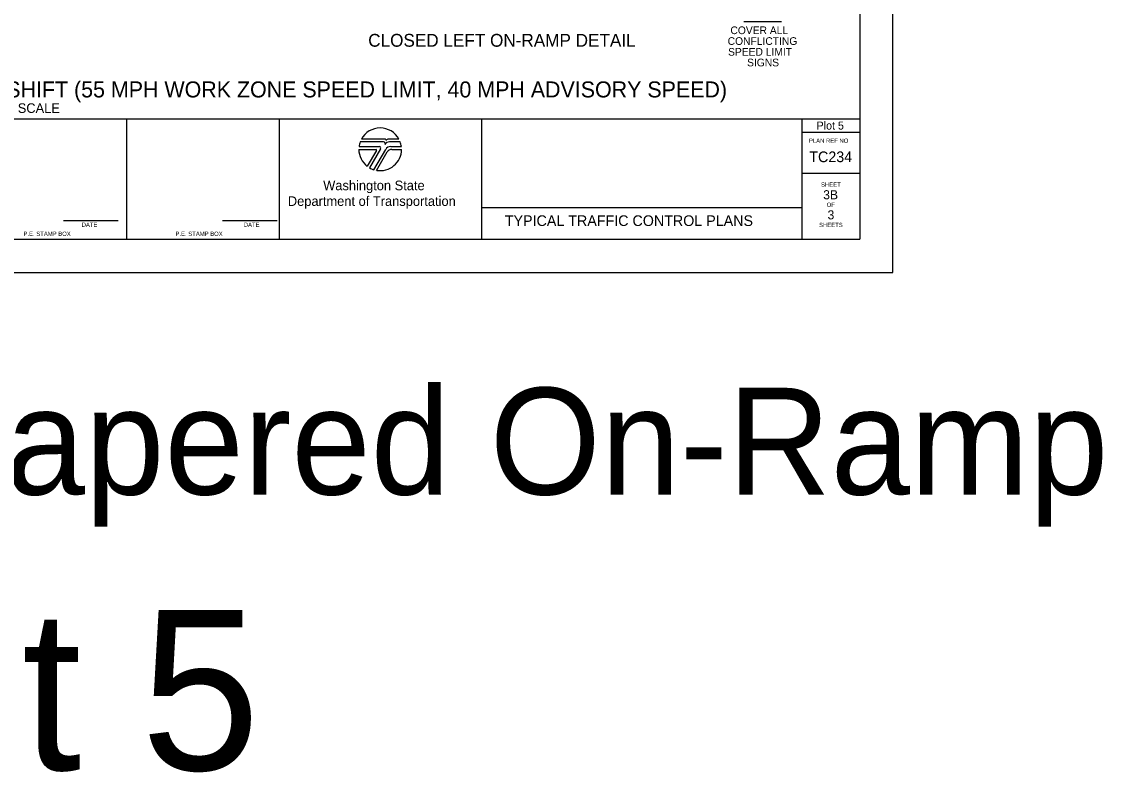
# Model space of a CAD drawing. Extents: x 99999 to 100116, y 99995 to 100013.
# Drawn here: x 100087.9 to 100098.02, y 99995.01 to 100002.04 of the extents above; entities that cross this region are included whole.
import ezdxf

# ---------------------------------------------------------------- set-up
doc = ezdxf.new("R2010")
doc.units = 0
for name, color, linetype in [('Default', 7, 'Continuous'), ('SH_DE_DetailHeading1Text', 7, 'Continuous'), ('SH_DE_DetailHeading2Text', 7, 'Continuous'), ('SH_GI_PlotLimits', 7, 'Continuous'), ('SH_GI_SheetBorder', 7, 'Continuous'), ('SH_GI_SheetLocationText', 7, 'Continuous'), ('SH_GI_SheetTextInCells', 7, 'Continuous'), ('SH_GI_TitleBlockText', 7, 'Continuous'), ('SH_GI_WSDOTLogo', 7, 'Continuous'), ('TR_SN_ConstructionSigns', 7, 'Continuous')]:
    doc.layers.add(name, color=color, linetype=linetype)

msp = doc.modelspace()

# ---------------------------------------------------------------- linework, layer by layer
at = {"layer": 'Default'}
msp.add_line((100094.663, 100002.036), (100095.018, 100002.036), dxfattribs=at)
at = {"layer": 'SH_GI_PlotLimits'}
msp.add_lwpolyline([(100079.062, 99999.687), (100096.062, 99999.687), (100096.062, 100010.687), (100079.062, 100010.687)], close=True, dxfattribs=at)
at = {"layer": 'SH_GI_SheetBorder'}
for p, q in [((100095.75, 100010.375), (100095.75, 100000)), ((100080, 100001.126), (100095.75, 100001.126)), ((100088.883, 100000), (100088.883, 100001.126)), ((100090.309, 100001.126), (100090.309, 100000)), ((100092.205, 100001.126), (100092.205, 100000)), ((100095.208, 100001.126), (100095.208, 100000)), ((100095.208, 100001.001), (100095.75, 100001.001)), ((100095.208, 100000.618), (100095.75, 100000.618)), ((100092.205, 100000.295), (100095.208, 100000.295)), ((100088.29, 100000.173), (100088.802, 100000.173)), ((100089.78, 100000.173), (100090.291, 100000.173)), ((100080, 100000), (100095.75, 100000))]:
    msp.add_line(p, q, dxfattribs=at)
at = {"layer": 'SH_GI_WSDOTLogo'}
for p, q in [((100091.059, 100000.866), (100091.25, 100000.866)), ((100091.289, 100000.909), (100091.07, 100000.909)), ((100091.303, 100000.935), (100091.081, 100000.935)), ((100091.433, 100000.935), (100091.335, 100000.935)), ((100091.445, 100000.909), (100091.343, 100000.909)), ((100091.343, 100000.909), (100091.343, 100000.909)), ((100091.356, 100000.866), (100091.456, 100000.866)), ((100091.057, 100000.84), (100091.215, 100000.84)), ((100091.222, 100000.828), (100091.136, 100000.681)), ((100091.261, 100000.846), (100091.157, 100000.667)), ((100091.199, 100000.649), (100091.309, 100000.839)), ((100091.224, 100000.643), (100091.324, 100000.816)), ((100091.365, 100000.839), (100091.457, 100000.839))]:
    msp.add_line(p, q, dxfattribs=at)
for centre, radius, start, end in [((100091.257, 100000.84), 0.2, 28.4787, 151.532), ((100091.257, 100000.84), 0.2, 159.696, 172.5057), ((100091.25, 100000.853), 0.0131, 329.7683, 90), ((100091.289, 100000.895), 0.0148, 327.8418, 89.9985), ((100091.343, 100000.861), 0.0484, 89.9953, 147.8238), ((100091.303, 100000.926), 0.00903, 329.8742, 90.0033), ((100091.356, 100000.812), 0.0542, 90, 149.9974), ((100091.335, 100000.907), 0.0287, 90.0072, 148.1676), ((100091.257, 100000.84), 0.2, 7.4943, 20.2941), ((100091.257, 100000.84), 0.2, 179.9986, 232.8433), ((100091.215, 100000.832), 0.0082, 329.7436, 90), ((100091.257, 100000.84), 0.2, 260.5455, 359.8086), ((100091.365, 100000.792), 0.0476, 90, 150.0543), ((100091.257, 100000.84), 0.2, 239.7929, 253.0448)]:
    msp.add_arc(centre, radius, start, end, dxfattribs=at)

# ---------------------------------------------------------------- texts
at = {"layer": 'SH_DE_DetailHeading1Text'}
for s, height, p in [("FREEWAY (2 LANES): SINGLE LEFT LANE CLOSURE, 9' MAX RIGHT SHOULDER SHIFT (55 MPH WORK ZONE SPEED LIMIT, 40 MPH ADVISORY SPEED)", 0.15, (100080.091, 100001.326)), ('NOT TO SCALE', 0.09, (100087.373, 100001.181))]:
    msp.add_text(s, height=height, rotation=360, dxfattribs=at).set_placement(p)
at = {"layer": 'SH_DE_DetailHeading2Text'}
msp.add_text('CLOSED LEFT ON-RAMP DETAIL', height=0.12, rotation=360, dxfattribs=at).set_placement((100091.145, 100001.801))
at = {"layer": 'SH_GI_SheetBorder'}
msp.add_text('PLAN REF NO', height=0.04003, dxfattribs=at).set_placement((100095.275, 100000.901))
at = {"layer": 'SH_GI_SheetLocationText'}
for s, height, p in [('Plot 5', 0.075, (100095.346, 100001.025)), ('Left Ramps: Tapered On-Ramp', 1, (100079.351, 99997.607)), ('Plot 5', 1.5, (100085.001, 99995.027))]:
    msp.add_text(s, height=height, dxfattribs=at).set_placement(p)
at = {"layer": 'SH_GI_SheetTextInCells'}
for s, height, p in [('Washington State', 0.09007, (100090.723, 100000.457)), ('SHEET', 0.04, (100095.388, 100000.49)), ('Department of Transportation', 0.09007, (100090.392, 100000.31)), ('OF', 0.04, (100095.441, 100000.301)), ('DATE', 0.04, (100088.46, 100000.114)), ('DATE', 0.04, (100089.979, 100000.114)), ('SHEETS', 0.04, (100095.37, 100000.112)), ('P.E. STAMP BOX', 0.04003, (100087.915, 100000.029)), ('P.E. STAMP BOX', 0.04003, (100089.339, 100000.029))]:
    msp.add_text(s, height=height, dxfattribs=at).set_placement(p)
at = {"layer": 'SH_GI_TitleBlockText'}
for s, height, p in [('TC234', 0.1, (100095.278, 100000.72)), ('3B', 0.085, (100095.408, 100000.372)), ('3', 0.085, (100095.449, 100000.184)), ('TYPICAL TRAFFIC CONTROL PLANS', 0.1, (100092.425, 100000.122))]:
    msp.add_text(s, height=height, dxfattribs=at).set_placement(p)
at = {"layer": 'TR_SN_ConstructionSigns'}
for s, p in [('COVER ALL', (100094.539, 100001.919)), ('CONFLICTING', (100094.513, 100001.818)), ('SPEED LIMIT', (100094.517, 100001.717)), ('SIGNS', (100094.695, 100001.617))]:
    msp.add_text(s, height=0.072, dxfattribs=at).set_placement(p)

doc.saveas('drawing.dxf')
